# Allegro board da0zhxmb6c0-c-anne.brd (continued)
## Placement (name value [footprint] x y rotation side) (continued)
PR77  0_4  [R0402]  136.16 111.76 180 bottom
PR78  2.26k/f_4  [R0402]  118.49 49.49 180 bottom
PR79  301/f_4  [R0402]  129.38 52.25 180 top
PR80  *0_4  [R0402]  136.16 110.8 180 bottom
PR81  619/f_4  [R0402]  118.63 48.22 270 bottom
PR82  100k/f_4  [R0402]  127.37 52.21 180 bottom
PR83  301/f_4  [R0402]  118.24 46.31 270 top
PR84  649/f_4  [R0402]  117.29 46.31 90 top
PR85  200/f_4  [R0402]  118.62 48.22 90 top
PR86  *4.7_6  [R0603]  89.67 24.35 270 top
PR87  0_4  [R0402]  116.71 51.4 0 bottom
PR88  1/f_4  [R0402]  129.38 52.25 0 bottom
PR89  976/f_4  [R0402]  116.71 50.45 180 top
PR90  100/j_4  [R0402]  35.54 47.36 0 bottom
PR91  10k_4  [R0402]  96.22 28.3 0 bottom
PR92  316k/f_4  [R0402]  95.51 29.3 0 bottom
PR93  0_4  [R0402]  122.43 48.22 90 top
PR94  2.1k/f_4  [R0402]  117.66 48.22 90 bottom
PR95  15.4k/f_4  [R0402]  124.75 48.22 270 top
PR96  0_4  [R0402]  87.51 27.56 180 bottom
PR97  0_4  [R0402]  87.51 28.45 180 bottom
PR98  0_4  [R0402]  121.48 48.22 270 bottom
PR99  274/f_4  [R0402]  125.7 48.22 270 top
PR100  7.5_6  [R0603]  100.73 27.07 0 top
PR101  10_6  [R0603]  97.99 26.54 180 top
PR102  100k/f_4  [R0402]  97.79 29.68 90 bottom
PR103  13.7k/f_4  [R0402]  125.7 46.46 270 top
PR104  *100k/f_4  [R0402]  34.75 53.56 90 top
PR105  *100k_4  [R0402]  98.83 29.68 90 bottom
PR106  0_4  [R0402]  122.43 48.22 90 bottom
PR107  64.9k/f_4  [R0402]  124.75 46.46 270 top
PR108  22_6  [R0603]  123.59 47.84 270 top
PR109  0_6  [R0603]  94.64 23.18 180 top
PR110  *0/short_4  [S0402]  35.38 53.54 270 bottom
PR111  10k/f_4  [R0402]  33.17 46.68 90 bottom
PR112  12k/f_4  [R0402]  34.42 53.54 90 bottom
PR113  0.01/f_0612  [RC3216]  80.65 27.65 90 bottom
PR114  *0/short_4  [S0402]  103.25 26.25 180 top
PR115  71.5k/f_4  [R0402]  33.46 53.53 90 bottom
PR116  30.1k/f_4  [R0402]  32.23 46.68 90 bottom
PR117  *0/short_4  [S0402]  103.25 25.36 180 top
PR118  *0/short_4  [S0402]  32.44 53.54 270 bottom
PR119  11k/f_4  [R0402]  98.55 21.17 90 bottom
PR120  2.2_6  [R0603]  28.62 52.39 270 bottom
PR121  *0/short_4  [S0402]  30.33 53.54 270 bottom
PR122  63.4k/f_4  [R0402]  102.5 21.69 0 top
PR123  10k_4  [R0402]  105.11 25.6 0 top
PR124  100k_4  [R0402]  101.6 19.65 270 top
PR125  100k_4  [R0402]  95.8 27.36 0 top
PR126  20_1206  [R1206]  87.86 24.84 90 top
PR127  0_6  [R0603]  104.8 21.88 0 top
PR128  *100k_4  [R0402]  102.62 26.63 270 bottom
PR129  0_4  [R0402]  105.12 26.59 180 top
PR130  *0_4  [R0402]  100.2 19.65 90 top
PR131  88.7k/f_4  [R0402]  103.03 23.06 180 top
PR132  0_4  [R0402]  30.3 46.67 270 bottom
PR133  *0_4  [R0402]  107.06 100.88 180 top
PR134  *0_4  [R0402]  114.36 105.95 90 top
PR135  *0/short_4  [S0402]  24 87.34 180 bottom
PR136  0.02/f_0612  [RC3216]  26.93 86.58 180 bottom
PR137  220_8  [R0805]  84.71 103.98 180 top
PR138  22_6  [R0603]  101.91 88.2 180 top
PR139  22_8  [R0805]  107.99 85.11 270 top
PR140  *0/short_4  [S0402]  24 86.1 180 bottom
PR141  *100k/f_6  [R0603]  118.39 103.22 180 top
PR142  1m_4  [R0402]  118.26 106.77 270 top
PR143  1m_4  [R0402]  98.55 98.77 90 top
PR144  1m_4  [R0402]  119.28 106.77 90 top
PR145  *0_6  [R0603]  144.4 94.64 180 top
PR146  0_6  [R0603]  144.4 96.01 0 top
PR147  100/f_4  [R0402]  42.55 83.66 0 top
PR148  *0/short_4  [S0402]  42.55 84.55 180 top
PR149  100/f_4  [R0402]  45.72 83.66 0 top
PR150  *0/short_4  [S0402]  45.72 84.67 0 top
PR151  0_4  [R0402]  45.21 60.54 0 bottom
PR152  150/f_4  [R0402]  46.74 59.65 270 bottom
PR153  10k/f_4  [R0402]  47.12 62.07 0 bottom
PR154  *0_4  [R0402]  45.09 69.56 180 top
PR155  10k/f_4  [R0402]  45.24 62.58 180 bottom
PR156  10k/f_4  [R0402]  137.52 97.02 180 bottom
PR157  10k/f_4  [R0402]  137.52 95.09 0 bottom
PR158  5.11k/f_4  [R0402]  45.24 61.56 0 bottom
PR159  20/f_4  [R0402]  47.12 61.05 180 bottom
PR160  3.57k/f_4  [R0402]  45.21 58.51 180 bottom
PR161  0_4  [R0402]  45.21 59.53 0 bottom
PR162  22_8  [R0805]  144.68 91.63 0 top
PR163  68k/f_4  [R0402]  44.2 61.2 0 top
PR164  *2.2_6  [R0603]  135.33 91.4 0 bottom
PR165  0_4  [R0402]  43 62.35 0 top
PR166  22_6  [R0603]  40.11 60.53 270 top
PR167  *665k/f_4  [R0402]  130.68 94.07 270 top
PR168  0_4  [R0402]  132.79 95.29 270 top
PR169  *0_4  [R0402]  130.18 95.36 180 top
PR170  2.2_6  [R0603]  38.46 69.94 180 top
PR171  *200/f_4  [R0402]  34.24 67.44 180 bottom
PR172  *75/f_4  [R0402]  36.87 64.84 270 top
PR173  6.98k/f_4  [R0402]  36.42 65.52 180 bottom
PR174  13.7k/f_4  [R0402]  36.42 63.44 0 bottom
PR175  1.1k/f_4  [R0402]  36.37 61.38 0 bottom
PR176  22.1k/f_4  [R0402]  38.71 61.08 90 bottom
PR177  100k/f_4  [R0402]  40.51 83.66 270 bottom
PR178  *1m_6  [R0603]  114.81 92.55 90 top
PR179  221/f_4  [R0402]  36.42 62.47 0 bottom
PR180  20/f_4  [R0402]  37.47 58.66 0 top
PR181  1k/f_4  [R0402]  37.77 59.02 90 bottom
PR182  *2.2_6  [R0603]  128.03 61.81 0 top
PR183  *22_8  [R0805]  116.84 85.33 270 top
PR184  *2.2_6  [R0603]  40.77 75.66 90 top
PR185  100k/f_4  [R0402]  123.48 57.78 270 bottom
PR186  *1m_6  [R0603]  116.21 92.55 90 top
PR187  200/f_4  [R0402]  34.32 67.43 180 top
PR188  301/f_4  [R0402]  34.24 66.47 0 bottom
PR189  *1m_6  [R0603]  111.76 92.55 90 top
PR190  *1m_6  [R0603]  113.23 92.55 90 top
PR191  2.2_4  [R0402]  127.12 56.35 180 bottom
PR192  *2.2_6  [R0603]  129.44 109.67 90 bottom
PR193  887k/f_4  [R0402]  127.37 56.35 0 top
PR194  22_8  [R0805]  105.62 110.86 0 top
PR195  0_4  [R0402]  118.48 54.7 180 bottom
PR196  10k/f_4  [R0402]  118.49 51.53 180 top
PR197  *200/f_4  [R0402]  129.38 53.29 0 top
PR198  6.98k/f_4  [R0402]  127.37 54.36 180 bottom
PR199  6.49k/f_4  [R0402]  127.37 55.4 180 bottom
PR200  *0/short_4  [S0402]  118.59 50.51 0 top
PR201  1m_6  [R0603]  97.66 104.87 270 top
PR202  16/f_4  [R0402]  116.71 51.4 180 top
PR203  402/f_4  [R0402]  129.38 53.29 180 bottom
PR204  *75/f_4  [R0402]  127.37 52.25 0 top
PR205  1.1k/f_4  [R0402]  125.7 48.22 90 bottom
PR206  64.9/f_4  [R0402]  125.7 46.46 270 bottom
PR207  *0_4  [R0402]  119.57 48.22 270 bottom
PR208  1.58k/f_4  [R0402]  124.75 46.46 90 bottom
PR209  22.1k/f_4  [R0402]  124.75 48.22 90 bottom
PR210  *0/short_4  [S0402]  111.01 61.81 180 top
PR211  100/f_4  [R0402]  111 60.67 180 top
PR212  68k/f_4  [R0402]  120.52 48.22 270 top
PR213  *0/short_4  [S0402]  111.01 62.83 180 top
PR214  10k/f_4  [R0402]  121.48 48.22 90 top
PR215  0_4  [R0402]  120.52 46.44 90 top
PR216  100/f_4  [R0402]  112.4 62.32 270 top
PR217  1m_6  [R0603]  102.5 109.4 0 top
PR218  *1m_6  [R0603]  105.07 109.17 180 top
PR219  1m_6  [R0603]  102.54 110.85 180 top
PR220  0_4  [R0402]  100.58 31.5 270 top
PR221  *10k_4  [R0402]  98.67 31.5 270 top
PR222  *0_4  [R0402]  99.62 31.5 90 top
PR223  1m_4  [R0402]  67.08 18.71 90 top
PR224  *0_4  [R0402]  68.35 18.68 270 top
PR225  100_4  [R0402]  74.04 20.46 90 top
PR226  100_4  [R0402]  69.42 20.46 90 top
PR227  100_4  [R0402]  68.35 20.46 90 top
PR228  100k_4  [R0402]  95.1 30.57 0 top
PR229  33k/f_4  [R0402]  86.17 23.58 270 top
PR230  10k_4  [R0402]  58.8 25.87 270 bottom
PR231  *2.2_6  [R0603]  26.37 44.7 180 top
PR232  0_4  [R0402]  115.25 105.95 90 top
PR233  *0_4  [R0402]  113.47 105.95 90 top
PR234  0_4  [R0402]  44.43 67.58 270 bottom
PR235  *0_4  [R0402]  43.36 71.34 270 top
PR236  *0_4  [R0402]  118.48 53.72 0 top
PR237  *0_4  [R0402]  31.37 53.56 270 bottom
PR238  22_6  [R0603]  101.91 89.6 180 top
PR239  100k/f_4  [R0402]  91.77 102.71 180 bottom
PR240  100k/f_4  [R0402]  91.77 103.72 180 bottom
PR241  100k/f_4  [R0402]  91.77 99.91 180 bottom
PR242  100k/f_4  [R0402]  91.77 100.93 180 bottom
PU1  rt5041agqw  [QFN28-4X4-4-29P-RT5041A]  113.77 101.74 0 bottom
PU2  as393mtr-e1  [SOIC8-6-1_27]  115.7 39.84 180 bottom
PU3  nb670gq-z  [QFN14-3X3-4-16P]  134.11 95.09 0 bottom
PU4  rt8175agqw  [QFN32-4X4-4-33P-RT8171B]  40.69 65.52 180 bottom
PU5  nb671gq-z  [QFN14-3X3-4-16P]  134.16 106.29 270 bottom
PU6  rt8175agqw  [QFN32-4X4-4-33P-RT8171B]  122.94 52.67 0 top
PU7  tps51716rukr  [TQFN20-3X3-4-21P]  31.98 50.1 270 bottom
PU8  bq24737rgrr  [PVQFN20-3_5X3_5-5-25P]  99.06 22.98 0 top
Q1  pj4n3kdw  [SC70-2_1-65-6P]  19.1 82.48 90 top
Q2  2n7002  [SOT23_213-3_3-2]  15.13 86.74 270 bottom
Q3  2n7002k  [SOT23_213-3_3-2]  41.91 25.62 0 bottom
Q5  2n7002k  [SOT23_213-3_3-2]  44.83 28.16 0 bottom
Q6  *2n7002dw  [SC70-2_1-65-6P]  7.49 29.61 180 top
Q7  *pja138k  [SOT23_213-3_3-2]  12.19 30.44 90 top
Q10  2n7002k  [SOT23_213-3_3-2]  72.9 102.07 90 top
Q11  *pja138k  [SOT23_213-3_3-2]  28.07 22.95 90 top
Q12  pja138k  [SOT23_213-3_3-2]  148.08 27.52 0 top
Q13  *pj4n3kdw  [SC70-2_1-65-6P]  149.61 38.7 90 top
Q14  ap2331sa-7  [SOT23_213-3_3-2]  14.99 86.55 270 top
Q15  pja138k  [SOT23_213-3_3-2]  34.32 93.36 0 bottom
Q16  2n7002k  [SOT23_213-3_3-2]  31.75 90.57 90 bottom
Q17  pja138k  [SOT23_213-3_3-2]  39.78 89.27 90 bottom
Q19  2n7002k  [SOT23_213-3_3-2]  19.02 75.53 0 top
Q21  2n7002k  [SOT23_213-3_3-2]  88.6 94.81 0 bottom
Q22  pja138k  [SOT23_213-3_3-2]  38.05 93.39 90 bottom
Q23  2n7002k  [SOT23_213-3_3-2]  82.93 90.9 270 bottom
Q24  dtc144eua  [UMT_213-3-1_3]  38.36 25.87 0 bottom
Q25  *ac@pja138k  [SOT23_213-3_3-2]  145.83 79.91 270 top
Q27  ac@ao3413  [SOT23_213-3_3-2]  151.92 102.75 270 top
Q31  mmbt3904-7-f_200ma  [SOT23_213-3_3-2]  140.72 100.68 0 top
Q32  *pja138k  [SOT23_213-3_3-2]  101.6 89.31 270 bottom
Q33  *pja138k  [SOT23_213-3_3-2]  98.71 93.08 270 top
Q34  *pja138k  [SOT23_213-3_3-2]  79 90.9 270 bottom
Q35  pj4n3kdw  [SC70-2_1-65-6P]  110.62 41.62 90 bottom
Q36  *pj4n3kdw  [SC70-2_1-65-6P]  102.88 82.66 90 bottom
Q38  pj4n3kdw  [SC70-2_1-65-6P]  106.31 82.79 90 bottom
Q39  dtc144eua  [UMT_213-3-1_3]  92.33 93.18 90 bottom
Q40  2n7002k  [SOT23_213-3_3-2]  126.69 40.9 270 bottom
Q41  2n7002  [SOT23_213-3_3-2]  41.4 25.36 0 top
Q42  2n7002  [SOT23_213-3_3-2]  39.37 22.7 180 top
Q43  gs@dtc144eua  [UMT_213-3-1_3]  89.41 82.64 270 top
Q44  2n7002k  [SOT23_213-3_3-2]  44.58 22.82 0 top
Q45  *ao3413  [SOT23_213-3_3-2]  48.97 24.54 0 top
Q53  *hd@pja138k  [SOT23_213-3_3-2]  148.87 58.38 90 top
Q54  *ao3413  [SOT23_213-3_3-2]  62.31 96.74 270 top
Q65  pja138k  [SOT23_213-3_3-2]  145.83 83.61 270 top
Q75  2n7002k  [SOT23_213-3_3-2]  96.9 89.12 90 bottom
Q76  2n7002k  [SOT23_213-3_3-2]  92.97 89.5 0 bottom
Q77  hub@ao3413  [SOT23_213-3_3-2]  25.91 29.68 270 top
Q78  hub@2n7002k  [SOT23_213-3_3-2]  22.73 31.46 90 top
Q79  pja138k  [SOT23_213-3_3-2]  104.99 88.61 0 top
R2  *100/f_4  [R0402]  14.1 79.18 270 bottom
R3  *100/f_4  [R0402]  14.1 81.21 270 bottom
R4  *100/f_4  [R0402]  14.1 75.12 270 bottom
R5  *100/f_4  [R0402]  14.1 77.15 270 bottom
R6  2.2k_4  [R0402]  19.31 85.05 180 top
R7  2.2k_4  [R0402]  19.31 80.07 0 top
R10  100k/f_4  [R0402]  16 83.88 270 bottom
R11  *0/short_4  [S0402]  16.28 53.23 180 bottom
R12  *0/short_4  [S0402]  16.28 54.25 180 bottom
R13  *0/short_4  [S0402]  16.36 59.81 180 bottom
R14  *0/short_4  [S0402]  16.36 60.82 180 bottom
R15  *0/short_4  [S0402]  16.28 56.66 180 bottom
R16  *0/short_4  [S0402]  16.28 57.67 180 bottom
R17  2.2_6  [R0603]  153.57 105.01 90 top
R18  *10k_4  [R0402]  54.87 72.13 0 bottom
R19  10k_4  [R0402]  17.63 86.96 90 bottom
R20  47/f_6  [R0603]  15.62 46.5 90 bottom
R21  47/f_6  [R0603]  15.62 43.84 270 bottom
R22  *10k_4  [R0402]  54.87 73.14 0 bottom
R23  4.7k_4  [R0402]  51.82 74.26 0 bottom
R25  10k_4  [R0402]  15.43 23.33 270 top
R26  4.7k_4  [R0402]  17.32 43.27 180 bottom
R28  4.7k_4  [R0402]  17.27 47.08 180 bottom
R29  200k/f_4  [R0402]  10.14 22.44 0 top
R30  4.7k_4  [R0402]  51.82 75.28 0 bottom
R32  4.7k_4  [R0402]  14.55 23.33 90 top
R33  10k_4  [R0402]  80.28 87.75 90 bottom
R34  10k_4  [R0402]  85.36 87.75 90 bottom
R35  *ac@10k_4  [R0402]  89.43 87.75 90 bottom
R36  *10k_4  [R0402]  88.42 87.75 90 bottom
R37  tpm@10k_4  [R0402]  87.4 87.75 90 bottom
R38  20k/j_4  [R0402]  143.89 99.72 0 top
R39  10k_4  [R0402]  96.32 78.21 270 top
R40  10k_4  [R0402]  86.38 87.75 90 bottom
R41  100k/j_4  [R0402]  11.94 22.44 0 top
R42  33_4  [R0402]  80.85 93.69 270 bottom
R43  *10k_4  [R0402]  54.87 71.08 0 bottom
R44  *0_4  [R0402]  56.52 86.96 180 bottom
R45  *0_4  [R0402]  56.52 85.82 180 bottom
R46  *20k/j_4  [R0402]  56.52 88.71 0 bottom
R47  4.7k_4  [R0402]  54.87 70.07 0 bottom
R48  *10k_4  [R0402]  51.82 73.24 0 bottom
R49  *0/short_6  [S0603]  76.58 88.48 270 bottom
R50  10k_4  [R0402]  87.5 81.88 90 bottom
R51  nac@10k_4  [R0402]  89.45 85.98 90 bottom
R52  10k_4  [R0402]  88.38 85.98 90 bottom
R53  ntpm@10k_4  [R0402]  87.39 85.98 90 bottom
R54  *10k_4  [R0402]  86.38 85.98 90 bottom
R55  *10k_4  [R0402]  84.73 85.98 90 bottom
R56  10k_4  [R0402]  92.84 82.98 180 top
R57  10k_4  [R0402]  77.8 88.08 270 bottom
R58  20k/j_4  [R0402]  145.67 99.72 180 top
R59  *10k_4  [R0402]  99.06 90.8 180 top
R60  113/f_4  [R0402]  58.66 86.1 90 bottom
R61  0_4  [R0402]  58.9 87.59 0 bottom
R62  *0_4  [R0402]  59.66 86.1 270 bottom
R63  22_4  [R0402]  16.26 19.99 270 top
R64  *10k_4  [R0402]  51.82 72.1 0 bottom
R65  2.2k_4  [R0402]  17.53 48.86 90 top
R66  2.2k_4  [R0402]  6.99 36.54 0 top
R67  100k/f_4  [R0402]  3.31 20.18 180 top
R68  10_4  [R0402]  119.64 90.01 180 bottom
R69  *10k_6_ntc  [R0603]  86.97 91.89 180 bottom
R70  10_4  [R0402]  104.14 88.74 270 bottom
R71  0_4  [R0402]  47.63 27.9 180 bottom
R72  0_4  [R0402]  47.63 28.79 180 bottom
R73  *100k_4  [R0402]  47.63 27.02 0 bottom
R74  *0_4  [R0402]  13.67 17.58 0 top
R75  10_4  [R0402]  119.64 88.99 180 bottom
R76  *1k/j_4  [R0402]  51.82 71.08 180 bottom
R77  3.3k/f_4  [R0402]  104.65 90.26 180 bottom
R78  *0/j_4  [R0402]  88.11 90.11 90 bottom
R79  *10k_4  [R0402]  85.95 90.11 90 bottom
R80  10k_4  [R0402]  89.13 85.93 270 top
R81  10k_4  [R0402]  94.5 84.77 90 bottom
R83  22_4  [R0402]  13.67 16.63 0 top
R84  10_4  [R0402]  120.27 87.59 270 bottom
R85  10_4  [R0402]  106.76 89.25 0 bottom
R92  3.3k/f_4  [R0402]  119.25 87.59 270 bottom
R93  *10k_4  [R0402]  53.34 70.2 270 bottom
R96  33_4  [R0402]  106.76 87.98 0 bottom
R97  100k_4  [R0402]  49.91 67.91 0 bottom
R98  10k_4  [R0402]  97.34 78.21 270 top
R99  10k_4  [R0402]  98.35 78.21 270 top
R100  100_4  [R0402]  77.9 77.54 270 top
R101  10k_4  [R0402]  92.06 81.14 90 top
R102  3.3k/f_4  [R0402]  105.33 88.28 90 bottom
R103  *4.7k_4  [R0402]  51.94 67.91 0 bottom
R104  *100k/f_4  [R0402]  68 95.44 180 top
R105  1k_4  [R0402]  27.43 19.65 0 top
R106  *0/short_4  [S0402]  74.4 98.19 270 top
R107  *100k/j_4  [R0402]  13.46 28.54 90 top
R108  *100k/f_4  [R0402]  69.83 95.44 0 top
R109  *0/short_4  [S0402]  73.38 98.19 270 top
R110  100k_4  [R0402]  48.02 73.4 180 bottom
R111  *10k_4  [R0402]  50.03 73.4 180 bottom
R112  22_4  [R0402]  92.6 79.03 0 bottom
R113  51/f_4  [R0402]  60.3 72.23 180 top
R114  *0_4  [R0402]  64.26 101.31 180 top
R115  51/f_4  [R0402]  51.18 72.86 270 top
R116  100k_4  [R0402]  48.02 74.42 180 bottom
R117  *10k_4  [R0402]  49.95 74.42 180 bottom
R118  hub@0_4  [R0402]  75.52 98.16 90 top
R119  hub@0_4  [R0402]  76.53 98.16 90 top
R120  *22_4  [R0402]  92.61 78.06 0 bottom
R121  tpm@22_4  [R0402]  94.38 78.54 0 bottom
R122  *10k_4  [R0402]  49.93 75.69 180 bottom
R123  100k_4  [R0402]  48.02 75.69 180 bottom
R124  *10k_4  [R0402]  15.37 29.43 180 top
R125  *100k_4  [R0402]  15.37 30.7 0 top
R126  22_4  [R0402]  90.85 77.84 0 bottom
R127  100k_4  [R0402]  49.91 66.77 0 bottom
R128  ac@10k_4  [R0402]  147.07 101.31 90 top
R129  *0_6  [R0603]  67.31 101.82 270 top
R130  0_6  [R0603]  68.84 101.82 270 top
R131  *10k_4  [R0402]  51.82 66.77 180 bottom
R132  20k_4  [R0402]  50 72.25 180 bottom
R135  tpm@2.2_6  [R0603]  127.64 70.96 270 bottom
R136  *0/short_4  [S0402]  47.99 71.31 180 bottom
R137  2.2/f_4  [R0402]  44.96 88.12 0 bottom
R138  *200/f_4  [R0402]  45.98 69.69 0 bottom
R139  0_4  [R0402]  43.94 69.69 0 bottom
R141  2.2/f_4  [R0402]  44.96 87.02 0 bottom
R142  200/f_4  [R0402]  45.98 70.58 0 bottom
R143  0_4  [R0402]  43.94 70.88 0 bottom
R144  2.2/f_4  [R0402]  43.11 87.02 180 bottom
R146  2.2/f_4  [R0402]  43.13 85.89 180 bottom
R147  *301/f_4  [R0402]  45.98 71.59 180 bottom
R148  0_4  [R0402]  43.94 71.9 0 bottom
R149  tpm_n@0_4  [R0402]  141.74 72.44 0 bottom
R150  *1k/j_4  [R0402]  88.43 75.47 180 bottom
R151  *1k/j_4  [R0402]  87.96 74.03 270 bottom
R154  *1k/j_4  [R0402]  90.82 74.56 270 bottom
R155  *1k/j_4  [R0402]  91.49 73.22 180 bottom
R156  *1k/j_4  [R0402]  89.71 72.3 180 bottom
R157  *1k/j_4  [R0402]  92.08 71.77 270 bottom
R158  *1k/j_4  [R0402]  93.17 71.77 270 bottom
R159  *tpm_i@0_4  [R0402]  141.35 71.1 90 bottom
R160  100k/f_4  [R0402]  91.85 85.08 270 bottom
R161  0_4  [R0402]  102.54 75.16 90 top
R163  *100k_4  [R0402]  98.68 87.72 180 bottom
R164  0_4  [R0402]  95.05 65.42 90 bottom
R165  10k_4  [R0402]  94.18 67.9 0 bottom
R166  0_4  [R0402]  91.83 86.78 270 bottom
R167  100k/f_4  [R0402]  101.52 75.16 90 top
R168  3.3k/f_4  [R0402]  136.27 56.48 90 bottom
R169  *0_4  [R0402]  96.55 72.76 90 bottom
R170  *10k_4  [R0402]  89.79 69.81 90 top
R171  *1k/j_4  [R0402]  94.18 70.31 180 bottom
R172  2.7k_4  [R0402]  94.18 69.36 0 bottom
R173  10k_4  [R0402]  93.42 66.89 180 bottom
R174  *1k_4  [R0402]  109.74 40.86 0 top
R175  3.3k/f_4  [R0402]  133.73 56.48 90 bottom
R176  0_4  [R0402]  133.42 40.05 270 bottom
R177  *0_4  [R0402]  92.84 86.78 270 bottom
R178  *0_4  [R0402]  103.68 75.16 90 top
R180  *1k/j_4  [R0402]  97.6 67.4 90 bottom
R181  *0/short_4  [S0402]  90.3 68.88 180 bottom
R182  10k/f_4  [R0402]  100.47 67.37 90 bottom
R183  *10k_4  [R0402]  138.91 50.38 270 bottom
R184  3.3k/f_4  [R0402]  134.11 43 270 bottom
R186  *1k/j_4  [R0402]  96.64 67.02 90 bottom
R188  0_4  [R0402]  94.52 75.51 0 bottom
R189  *1k/j_4  [R0402]  99.5 67.4 90 bottom
R191  0_4  [R0402]  94.87 73.4 0 bottom
R193  *1k/j_4  [R0402]  98.55 67.4 90 bottom
R194  1k/j_4  [R0402]  99.53 65.54 270 bottom
R196  1k/j_4  [R0402]  88.48 65.9 0 top
R197  *1k_4  [R0402]  111.73 39.59 0 top
R198  1k/j_4  [R0402]  98.32 65.54 270 bottom
R199  *1k_4  [R0402]  109.74 39.72 180 top
R200  *10k_4  [R0402]  80.07 68.56 90 top
R201  *10k_4  [R0402]  90.93 69.81 90 top
R202  75/f_4  [R0402]  98.22 71.54 180 bottom
R203  75/f_4  [R0402]  99.21 69.23 180 bottom
R206  75/f_4  [R0402]  96.65 69.13 180 bottom
R208  75/f_4  [R0402]  98.55 70.42 180 bottom
R209  0_4  [R0402]  127 42.89 90 top
R210  100k_4  [R0402]  131.95 43.27 270 top
R212  4.7k_4  [R0402]  137.16 43.27 270 top
R213  4.7k_4  [R0402]  138.11 43.27 270 top
R214  10k_4  [R0402]  138.81 45.81 270 top
R215  *4.7k_4  [R0402]  134.11 43.27 270 top
R216  *4.7k_4  [R0402]  135.25 43.27 270 top
R218  *10k_4  [R0402]  136.69 43.65 0 bottom
R220  *0/short_4  [S0402]  93.55 84.22 90 bottom
R221  10k_4  [R0402]  97.21 84.91 270 bottom
R222  0_4  [R0402]  145.42 33.14 90 top
R223  10k_4  [R0402]  96.12 64.41 90 bottom
R224  10k_4  [R0402]  102.36 68.16 0 top
R225  10k_4  [R0402]  100.84 69.56 90 top
R226  10k_4  [R0402]  102.36 69.18 0 top
R227  10k/f_4  [R0402]  70.36 102.2 90 top
R231  10k_4  [R0402]  94.02 82.21 90 bottom
R232  *0_4  [R0402]  96.1 84.9 270 bottom
R233  0_4  [R0402]  145.8 35.37 180 top
R235  *10k_4  [R0402]  123.95 31.59 0 top
R236  *0_4  [R0402]  137.15 77.31 0 top
R238  *0_4  [R0402]  132.15 78.99 0 top
R239  *0_4  [R0402]  131.77 79.96 0 top
R241  *0_4  [R0402]  133.47 77.16 90 top
R244  0_4  [R0402]  145.34 30.34 270 top
R245  *0_4  [R0402]  137.16 76.36 0 top
R247  0_4  [R0402]  132.59 36.41 90 bottom
R248  10k_4  [R0402]  146.36 30.34 270 top
R249  *22_4  [R0402]  128.61 36.41 270 bottom
R250  100k_4  [R0402]  131.24 36.41 270 bottom
R252  *10k_4  [R0402]  27.43 20.54 180 top
R254  100k_4  [R0402]  123.95 26.76 0 top
R255  *0_4  [R0402]  123.95 25.75 0 top
R256  0_4  [R0402]  123.95 24.6 180 top
R257  *10k_4  [R0402]  148.08 42.38 90 top
R259  *0_4  [R0402]  150.12 42.38 90 top
R260  0_6  [R0603]  32.74 26.84 180 top
R261  0_6  [R0603]  32.74 25.06 180 top
R262  0_6  [R0603]  32.74 23.41 180 top
R263  0_6  [R0603]  32.74 21.63 180 top
R266  33_4  [R0402]  7.7 4.94 270 top
R267  150/f_4  [R0402]  6.88 3.04 270 top
R268  2.2k_4  [R0402]  17.27 82.36 270 bottom
R269  2.2k_4  [R0402]  17.27 84.14 90 bottom
R270  620/f_4  [R0402]  14.48 77.66 0 top
R271  620/f_4  [R0402]  14.48 76.64 0 top
R272  620/f_4  [R0402]  14.48 75.63 0 top
R273  620/f_4  [R0402]  14.48 74.61 0 top
R274  620/f_4  [R0402]  14.48 81.72 0 top
R275  620/f_4  [R0402]  14.48 80.71 0 top
R276  620/f_4  [R0402]  14.48 79.69 0 top
R277  620/f_4  [R0402]  14.48 78.67 0 top
R278  *0_4  [R0402]  42.57 92.83 270 bottom
R279  10k_4  [R0402]  36.07 95.98 180 bottom
R280  *100k_4  [R0402]  42.55 90.92 90 bottom
R281  *100k_4  [R0402]  152.04 100.32 180 top
R282  10k_4  [R0402]  40.49 86.96 180 bottom
R289  *100k/f_4  [R0402]  21.46 75.5 270 top
R290  *100k_4  [R0402]  35.61 90.92 0 bottom
R293  10k_4  [R0402]  38.74 27.9 0 bottom
R294  *100k_4  [R0402]  41.12 93.56 0 bottom
R295  *0/short_4  [S0402]  31.37 93.06 180 bottom
R297  *ac@0_4  [R0402]  155.7 100.04 0 top
R299  10k_4  [R0402]  84.62 92.44 180 bottom
R300  10k_4  [R0402]  40.84 91.84 180 bottom
R301  *10k_4  [R0402]  38.74 28.79 180 bottom
R302  nac@0_4  [R0402]  153.82 98.97 0 top
R303  *0_6  [R0603]  86.36 86.71 90 top
R304  10m_4  [R0402]  73.28 86.96 180 bottom
R305  *10k_4  [R0402]  78.26 85.97 90 bottom
R306  *10k_4  [R0402]  40.77 28.79 180 bottom
R307  *10k_4  [R0402]  78.88 87.75 90 bottom
R308  0_4  [R0402]  84.46 87.72 90 bottom
R309  0_6  [R0603]  84.84 86.71 90 top
R310  10k_4  [R0402]  40.77 27.9 180 bottom
R311  200k/f_4  [R0402]  70.22 85.56 0 bottom
R312  *0/short_6  [S0603]  58.55 78.7 90 top
R313  *short_8  [S0805]  53.98 80.23 180 top
R314  *0/short_6  [S0603]  54.36 73.88 0 top
R315  *0/short_6  [S0603]  53.62 72 0 top
R316  *0/short_6  [S0603]  53.34 84.04 90 top
R317  10k_4  [R0402]  109.42 100.88 0 top
R318  0_6  [R0603]  82.93 86.71 90 top
R319  *short_8  [S0805]  70.87 85.44 90 top
R320  *10k_4  [R0402]  106.87 79.47 270 bottom
R321  0_4  [R0402]  8.64 36.16 90 top
R322  *1k_4  [R0402]  92.46 95.47 0 bottom
R323  *0/short_6  [S0603]  66.47 87.87 180 top
R324  *0/short_6  [S0603]  80.42 87.04 270 top
R325  *0/short_6  [S0603]  75.19 86.96 270 top
R326  *0/short_6  [S0603]  76.84 86.96 270 top
R327  0_4  [R0402]  18.16 41.32 180 bottom
R328  0_4  [R0402]  89.03 81.24 0 bottom
R329  *0_4  [R0402]  89.03 82.26 0 bottom
R331  *ac@4.7k_4  [R0402]  148.08 80.23 270 top
R332  *0_4  [R0402]  137.16 75.4 0 top
R333  *49.9/f_4  [R0402]  63.88 81.75 180 top
R334  *0/short_6  [S0603]  53.98 78.32 0 top
R336  *0/short_4  [S0402]  10.16 25.87 180 top
R337  nac@0_8  [R0805]  148.31 104.14 180 top
R338  *0/short_6  [S0603]  53.98 82.01 0 top
R339  *0/short_4  [S0402]  18.16 41.11 180 top
R340  10k/f_4  [R0402]  74.02 82.3 270 top
R341  402/f_4  [R0402]  62.49 79.59 270 top
R342  402/f_4  [R0402]  66.29 79.97 90 top
R343  402/f_4  [R0402]  68.96 81.88 180 top
R344  402/f_4  [R0402]  71.63 80.61 90 top
R346  80.6_4  [R0402]  81.56 78.33 90 top
R347  *0/short_6  [S0603]  60.07 76.29 0 top
R349  *10k_4  [R0402]  80.06 78.3 270 top
R350  *0/short_4  [S0402]  10.17 24.92 180 top
R351  *ac@0_4  [R0402]  142.69 76.31 270 top
R352  45.3/f_4  [R0402]  64.84 77.41 90 top
R353  *0/short_6  [S0603]  89.64 79.05 180 top
R354  *0/short_6  [S0603]  55.63 75.28 0 top
R355  402/f_4  [R0402]  69.44 78.45 90 top
R356  51/f_4  [R0402]  49.93 70.2 180 bottom
R357  51/f_4  [R0402]  52.2 74.64 270 top
R358  51/f_4  [R0402]  51.18 74.64 270 top
R359  10k_4  [R0402]  49.93 68.96 180 bottom
R360  *0_4  [R0402]  143.71 76.31 270 top
R361  49.9/f_4  [R0402]  75.08 77.76 90 top
R362  0_4  [R0402]  83.57 77.94 270 top
R363  100/f_4  [R0402]  85.19 76.55 180 top
R364  *0/short_6  [S0603]  89.64 77.53 180 top
R365  *short_8  [S0805]  61.98 88.23 90 top
R366  150_4  [R0402]  61.9 75.9 90 top
R367  *10k_4  [R0402]  48.02 68.96 180 bottom
R368  100/f_4  [R0402]  62.36 69.81 180 top
R369  2.49k/f_4  [R0402]  73.29 76.85 180 top
R376  *100k_4  [R0402]  149.23 99.91 270 top
R377  *short_8  [S0805]  63.96 88.23 90 top
R378  100k/f_4  [R0402]  71.88 98.52 270 top
R381  *0/short_6  [S0603]  78.86 87.03 270 top
R382  *0/short_4  [S0402]  66.42 95.39 270 top
R384  *100k/j_4  [R0402]  47.98 89.69 180 bottom
R385  *short_8  [S0805]  65.43 93.26 180 bottom
R386  *0_4  [R0402]  70.23 73.12 90 top
R388  *0/short_4  [S0402]  19.18 28.98 180 bottom
R389  *0/short_4  [S0402]  19.6 30.95 180 bottom
R390  *0/short_4  [S0402]  19.6 32.95 180 bottom
R392  *0/short_4  [S0402]  18.84 21.25 270 bottom
R394  0_4  [R0402]  19.18 28.03 0 bottom
R395  *short_8  [S0805]  53.87 70.42 180 top
R396  *tpm_i@20k_4  [R0402]  139.83 74.13 0 bottom
R398  *0_6  [R0603]  93.83 67.82 0 top
R399  *tpm_i@4.7k_4  [R0402]  139.84 71.47 180 bottom
R400  150k/f_4  [R0402]  142.11 97.81 0 top
R401  *tpm_i@10k_4  [R0402]  128.6 83.35 0 bottom
R402  0_6  [R0603]  93.45 66.41 0 top
R403  *tpm_i@4.7k_4  [R0402]  139.45 72.8 270 bottom
R405  *short_8  [S0805]  57.68 93.16 270 bottom
R406  *short_8  [S0805]  55.73 93.16 270 bottom
R407  68.1k/f_4  [R0402]  142.11 96.85 180 top
R408  *tpm_i@0_4  [R0402]  139.83 74.14 180 top
R409  51/f_4  [R0402]  48.02 67.94 0 bottom
R410  4.7k/j_4  [R0402]  140.08 96.85 0 top
R411  4.7k/j_4  [R0402]  140.08 98.31 180 top
R414  *0/short_6  [S0603]  101.36 65.94 90 top
R415  tpm_n@0_4  [R0402]  129.03 69.05 270 bottom
R416  10k_4  [R0402]  90.43 91.79 90 bottom
R417  *0/short_6  [S0603]  99.99 65.94 90 top
R418  1k/j_4  [R0402]  89.43 68.43 0 top
R419  1k/j_4  [R0402]  89.3 67.48 0 top
R420  0_4  [R0402]  99.29 90.57 270 bottom
R421  182_4  [R0402]  71.71 63.82 270 top
R422  182/f_4  [R0402]  71.3 58.92 180 top
R423  *0/short_6  [S0603]  92.33 78.05 180 top
R424  *0/short_6  [S0603]  88.4 64.33 180 top
R425  *0/short_6  [S0603]  93.46 65 180 top
R426  *0/short_6  [S0603]  93.46 63.56 180 top
R427  *10k_4  [R0402]  99.91 85.75 180 bottom
R428  *10k_4  [R0402]  99.87 79.84 0 bottom
R429  *10k_4  [R0402]  100.97 92.32 270 top
R430  *10k_4  [R0402]  76.58 90.77 270 bottom
R431  0_4  [R0402]  98.04 86.39 180 bottom
R432  gs@4.7k_4  [R0402]  113.72 52.67 270 top
R433  gs@200k/f_4  [R0402]  114.67 52.67 270 top
R434  gs@4.7k_4  [R0402]  112.64 52.67 270 top
R435  *10k_4  [R0402]  126.05 42.89 270 top
R436  *0/short_6  [S0603]  71.3 46.93 90 bottom
R437  *0/short_6  [S0603]  72.77 46.95 90 bottom
R439  *10k_4  [R0402]  104.53 84.56 270 bottom
R440  10k_4  [R0402]  140.75 45.81 90 top
R441  *10k_4  [R0402]  102.76 85.25 0 bottom
R444  *0/short_6  [S0603]  97.49 64.91 180 top
R446  8987@0_6  [R0603]  136.02 39.84 90 bottom
R450  0_8  [R0805]  150.35 63.97 90 top
R451  0_4  [R0402]  104.42 82.28 270 bottom
R452  0_4  [R0402]  104.97 79.43 90 bottom
R453  0_4  [R0402]  100.97 83.55 90 bottom
R454  *0_6  [R0603]  137.8 36.97 270 bottom
R457  10k_4  [R0402]  108.71 40.86 270 bottom
R459  *2.2_6  [R0603]  123.57 38.03 180 top
R460  2.2_6  [R0603]  144.04 37.76 0 bottom
R461  *10k_4  [R0402]  100.97 81.52 90 bottom
R463  4.7k_4  [R0402]  111.01 44.67 0 bottom
R465  10k_4  [R0402]  105.92 79.43 90 bottom
R468  100k_4  [R0402]  119.79 34.74 90 top
R470  4.7k_4  [R0402]  105.86 85.33 180 bottom
R479  1k/j_4  [R0402]  141.73 103.22 0 top
R481  10k_4  [R0402]  136.44 51.09 90 top
R486  gs@0_6  [R0603]  120.65 26 0 top
R489  *0_4  [R0402]  91.4 83.1 90 top
R490  em@10k_4  [R0402]  106.49 75.74 0 bottom
R491  *10k_4  [R0402]  102.16 79.89 0 bottom
R493  10k_4  [R0402]  46.23 26 180 top
R494  *0_4  [R0402]  90.42 76.68 180 bottom
R495  10k_4  [R0402]  46.23 24.98 180 top
R496  200k/f_4  [R0402]  110.75 52.92 90 top
R497  *0_4  [R0402]  50.67 26.63 90 bottom
R498  *10k_4  [R0402]  109.53 48.1 0 bottom
R499  10k_4  [R0402]  109.53 46.19 0 bottom
R500  *em@10k_4  [R0402]  118.49 78.45 90 top
R501  *0_8  [R0805]  53.98 26 90 bottom
R502  2.2k_4  [R0402]  108.71 52.92 270 top
R503  em@0_4  [R0402]  114.17 78.7 90 top
R504  gs@10k_4  [R0402]  89.28 80.36 0 top
R505  *0_4  [R0402]  42.04 21.43 0 top
R506  2.2k_4  [R0402]  109.73 52.92 270 top
R507  0_8  [R0805]  52.07 26 90 bottom
R510  0_6  [R0603]  50.42 24.48 90 bottom
R512  10k_4  [R0402]  45.59 20.16 90 top
R513  10k_4  [R0402]  46.61 20.16 90 top
R514  gs@0_4  [R0402]  120.27 24.84 0 top
R517  em@0_4  [R0402]  119.38 72.74 0 top
R578  *hd@0_4  [R0402]  152.53 68.59 0 top
R581  *100_4  [R0402]  54.87 74.16 0 bottom
R587  33_4  [R0402]  40.39 19.78 180 top
R588  33_4  [R0402]  42.8 20.03 180 top
R598  10k_4  [R0402]  148.08 83.44 270 top
R671  *0/short_4  [S0402]  143.77 84.8 270 top
R780  *0_4  [R0402]  60.22 98.95 270 top
R781  gs@0_6  [R0603]  62.23 101.56 90 top
R782  *100k_4  [R0402]  61.19 98.95 90 top
R816  33_4  [R0402]  110.34 34.59 270 bottom
R819  33_4  [R0402]  69.85 98.52 90 top
R821  33_4  [R0402]  155.7 98.97 0 top
R990  *47k_4  [R0402]  140.57 109.47 0 top
R991  *47k_4  [R0402]  140.57 108.4 0 top
R998  100k_4  [R0402]  151.64 27.9 90 top
R999  33_4  [R0402]  155.7 97.88 0 top
R1000  33_4  [R0402]  76.76 93.61 270 bottom
R1001  33_4  [R0402]  158.12 103.34 90 top
R1005  ssd_m2_ssd@0_8  [R0805]  148.59 55.46 0 top
R1007  *10k_4  [R0402]  48.02 70.16 180 bottom
R1008  *10k_4  [R0402]  49.93 71.24 180 bottom
R1009  4.7k_4  [R0402]  51.82 68.93 0 bottom
R1010  *4.7k_4  [R0402]  51.82 69.94 0 bottom
R1011  *10k_4  [R0402]  80.58 85.96 270 bottom
R1012  *tpm_n@10k_4  [R0402]  139.45 72.8 90 top
R1013  *tpm_i@0_4  [R0402]  128.4 79.85 0 bottom
R1014  *0/short_6  [S0603]  11.53 23.87 0 top
R1017  *em@10k_4  [R0402]  116.92 76.83 0 top
R1018  *0/short_4  [S0402]  93.68 65.81 180 bottom
R1019  *0_4  [R0402]  93.68 64.86 0 bottom
R1020  *ssd@0_6  [R0603]  152.77 57.67 90 top
R1021  *hd@0_6  [R0603]  151.38 57.67 90 top
R1022  *hd@10k_4  [R0402]  146.48 56.61 270 top
R1023  4.7k_4  [R0402]  135.22 45.68 270 top
R1024  4.7k_4  [R0402]  134.1 45.68 270 top
R1025  *hd@0_4  [R0402]  146.48 58.46 270 top
R1026  gs@10k_4  [R0402]  83.33 87.75 90 bottom
R1027  ngs@10k_4  [R0402]  83.69 85.97 90 bottom
R1028  *10k_4  [R0402]  19.69 39.06 0 top
R1029  *0_4  [R0402]  100.84 90.8 0 top
R1030  2.2_6  [R0603]  123.57 36.67 180 top
R1031  *0_4  [R0402]  89.03 83.28 0 bottom
R1035  100k/f_4  [R0402]  94.36 86.83 180 bottom
R1037  *22_8  [R0805]  151.77 41.62 90 top
R1038  *0_4  [R0402]  151.77 37.81 270 top
R1039  100k/f_4  [R0402]  96.14 91.53 0 bottom
R1040  4.7k/f_4  [R0402]  36.97 44.49 180 bottom
R1041  4.7k/f_4  [R0402]  36.97 43.22 0 bottom
R1042  4.7k/f_4  [R0402]  37.23 45.12 270 top
R1043  *short_6  [S0603]  51.77 30.42 270 top
R1044  4.7k/f_4  [R0402]  37.23 47.03 270 top
R1045  240/f_4  [R0402]  39.17 43.88 270 bottom
R1046  240/f_4  [R0402]  50.75 36.43 270 top
R1047  240/f_4  [R0402]  56.93 41.72 270 bottom
R1048  240/f_4  [R0402]  71.04 42.38 270 top
R1049  80.6/f_4  [R0402]  53.66 41.44 0 bottom
R1050  80.6/f_4  [R0402]  56.61 37.98 270 top
R1051  80.6/f_4  [R0402]  56.5 39.52 0 top
R1052  80.6/f_4  [R0402]  56.51 35.9 270 top
R1053  80.6/f_4  [R0402]  55.76 39.97 0 bottom
R1054  80.6/f_4  [R0402]  55.59 44.01 180 bottom
R1055  80.6/f_4  [R0402]  56.96 43.63 270 bottom
R1056  80.6/f_4  [R0402]  55.76 39.02 0 bottom
R1057  80.6/f_4  [R0402]  52.88 35.16 270 top
R1058  80.6/f_4  [R0402]  58.82 36.56 270 top
R1059  80.6/f_4  [R0402]  54.57 48.51 180 bottom
R1060  80.6/f_4  [R0402]  56.98 43.86 270 top
R1061  80.6/f_4  [R0402]  56.97 41.03 270 top
R1062  80.6/f_4  [R0402]  56.6 42.46 0 top
R1063  80.6/f_4  [R0402]  53.31 40.04 270 bottom
R1064  80.6/f_4  [R0402]  53.75 46.25 180 bottom
R1065  80.6/f_4  [R0402]  54.18 34.25 270 top
R1066  80.6/f_4  [R0402]  51.92 36.51 270 bottom
R1067  80.6/f_4  [R0402]  51.87 36.43 270 top
R1068  80.6/f_4  [R0402]  54.1 43.46 90 bottom
R1069  80.6/f_4  [R0402]  54.81 36.15 270 top
R1070  80.6/f_4  [R0402]  53.5 45.21 0 bottom
R1071  80.6/f_4  [R0402]  55.49 45.26 180 bottom
R1072  80.6/f_4  [R0402]  53.39 37.6 270 bottom
R1073  80.6/f_4  [R0402]  54.57 47.52 180 bottom
R1074  80.6/f_4  [R0402]  56.93 50.27 90 top
R1075  80.6/f_4  [R0402]  56 50.27 90 top
R1076  chb@240/f_4  [R0402]  94.94 36.18 270 bottom
R1077  chb@240/f_4  [R0402]  74.22 44.94 90 bottom
R1078  chb@240/f_4  [R0402]  85.82 36.46 270 top
R1079  chb@80.6/f_4  [R0402]  94.79 35.39 270 top
R1080  chb@80.6/f_4  [R0402]  89.73 39 270 bottom
R1081  chb@80.6/f_4  [R0402]  91.63 39.87 180 bottom
R1082  chb@80.6/f_4  [R0402]  88.37 41.3 270 bottom
R1083  chb@80.6/f_4  [R0402]  91.25 38.2 180 bottom
R1084  chb@80.6/f_4  [R0402]  90.58 36.15 270 top
R1085  chb@80.6/f_4  [R0402]  90.68 42.93 180 bottom
R1086  chb@80.6/f_4  [R0402]  90.53 46.76 0 bottom
R1087  chb@80.6/f_4  [R0402]  90.97 41.95 180 bottom
R1088  chb@80.6/f_4  [R0402]  92.02 43.49 270 bottom
R1089  chb@80.6/f_4  [R0402]  95.83 35.39 270 top
R1090  chb@80.6/f_4  [R0402]  88.26 41.21 270 top
R1091  chb@80.6/f_4  [R0402]  90.79 40.91 180 bottom
R1092  chb@80.6/f_4  [R0402]  92.52 35.29 270 top
R1093  chb@80.6/f_4  [R0402]  88.24 36.15 270 top
R1094  chb@80.6/f_4  [R0402]  88.66 44.94 270 top
R1095  chb@80.6/f_4  [R0402]  91.65 44.9 0 bottom
R1096  chb@80.6/f_4  [R0402]  91.63 35.36 270 top
R1097  chb@80.6/f_4  [R0402]  88.29 39.35 270 top
R1098  chb@80.6/f_4  [R0402]  88.71 37.84 180 top
R1099  chb@80.6/f_4  [R0402]  89.28 36.15 270 top
R1100  chb@80.6/f_4  [R0402]  89.3 39.35 270 top
R1101  chb@80.6/f_4  [R0402]  93.41 35.36 270 top
R1102  chb@80.6/f_4  [R0402]  88.62 44.84 270 bottom
R1103  chb@80.6/f_4  [R0402]  90.02 45.76 0 bottom
R1104  chb@240/f_4  [R0402]  102.82 36.43 270 top
R1105  chb@80.6/f_4  [R0402]  89.81 48.68 0 bottom
R1106  chb@80.6/f_4  [R0402]  89.81 47.77 0 bottom
R1107  chb@4.7k/f_4  [R0402]  108.72 44.16 180 bottom
R1108  chb@4.7k/f_4  [R0402]  108.71 42.64 270 bottom
R1113  hub@0_4  [R0402]  33.15 63.34 90 top
R1114  *10k_4  [R0402]  29.34 68.54 270 bottom
R1115  *10k_4  [R0402]  28.32 68.54 270 bottom
R1116  *0/j_4  [R0402]  31.5 70.32 270 bottom
R1117  *10k_4  [R0402]  23.88 65.5 0 bottom
R1118  *10k_4  [R0402]  23.88 64.48 0 bottom
R1119  hub@10k_4  [R0402]  23.88 68.8 0 bottom
R1120  hub@100k/f_4  [R0402]  26.29 68.54 90 bottom
R1121  hub@619/f_4  [R0402]  33.78 60.42 90 top
R1122  hub@0_4  [R0402]  23.88 66.64 0 bottom
R1123  hub@10k_4  [R0402]  23.88 62.7 0 bottom
R1124  *0/j_4  [R0402]  23.75 59.65 270 bottom
R1125  *47k_4  [R0402]  24.89 59.65 270 bottom
R1126  *0_6  [R0603]  86.56 82.36 0 top
R1127  0_6  [R0603]  86.56 83.89 0 top
R1128  *1k/j_4  [R0402]  88.91 74.03 270 bottom
R1129  *1k/j_4  [R0402]  89.87 74.56 270 bottom
R1136  hub@0_4  [R0402]  34.42 62.96 270 bottom
R1137  hub@0_4  [R0402]  33.4 62.96 270 bottom
R1138  nts@0_4  [R0402]  34.42 60.42 90 bottom
R1139  nts@0_4  [R0402]  33.4 60.42 90 bottom
R1140  hub@0_4  [R0402]  27.69 57.75 90 bottom
R1141  hub@0_4  [R0402]  26.8 57.75 90 bottom
R1142  nts@0_4  [R0402]  26.8 55.59 270 bottom
R1143  nts@0_4  [R0402]  27.69 55.59 270 bottom
R1144  nts@0_8  [R0805]  30.35 30.83 90 bottom
R1145  *0/short_4  [S0402]  17.81 21.24 270 top
R1146  *0/short_4  [S0402]  20.94 21.25 270 bottom
R1147  *0/short_4  [S0402]  20.74 21.24 270 top
R1148  6.2k/f_4  [R0402]  22.76 28.41 0 bottom
R1149  *330_4  [R0402]  19.18 27.08 180 bottom
R1150  m2_ssd@0_8  [R0805]  151.26 54.44 270 top
R1152  *0_4  [R0402]  145.8 38.26 180 top
R1153  *0_4  [R0402]  145.8 37.3 180 top
R1157  *8390@0_6  [R0603]  139.19 39.84 90 bottom
R1158  8987@0_4  [R0402]  139.07 43.27 270 top
R1159  *8390@0_4  [R0402]  137.8 45.81 270 top
R1161  8987@0_6  [R0603]  134.72 36.97 270 bottom
R1162  *8390@0_6  [R0603]  134.62 39.84 90 bottom
R1163  8987@0_4  [R0402]  133.16 43.27 90 top
R1164  8987@0_4  [R0402]  130.05 43.27 90 top
R1165  *8390@0_4  [R0402]  131 43.27 90 top
R1166  *8390@0_4  [R0402]  127.95 43.27 90 top
R1167  8987@0_4  [R0402]  128.91 43.27 90 top
R1171  nlid@0_4  [R0402]  145.8 27.14 270 top
R1172  *4.7k_4  [R0402]  145.8 36.35 180 top
R1173  *4.7k_4  [R0402]  145.8 39.21 180 top
R1175  0_4  [R0402]  119.79 33.04 90 top
R1177  0_6  [R0603]  145.02 42.56 90 top
R1178  *0_6  [R0603]  146.41 42.56 90 top
R1179  *0_4  [R0402]  131.79 42.22 270 bottom
R1180  sp@10k_4  [R0402]  82.32 87.78 90 bottom
R1181  sp@10k_4  [R0402]  82.69 85.95 90 bottom
R1182  sp@10k_4  [R0402]  81.33 87.77 90 bottom
R1183  sp@10k_4  [R0402]  81.64 85.96 90 bottom
R1184  sp@10k_4  [R0402]  95.31 78.21 90 top
R1185  sp@10k_4  [R0402]  95.01 75.33 90 top
R1186  sp@10k_4  [R0402]  94.22 78.23 90 top
R1187  sp@10k_4  [R0402]  94.06 75.33 90 top
R1188  *1k_4  [R0402]  115.31 47.46 0 top
R1189  *1k_4  [R0402]  115.31 46.39 0 top
R1190  *0_4  [R0402]  113.72 50.64 90 top
R1191  *0_4  [R0402]  112.64 50.64 90 top
R1192  *1k_4  [R0402]  115.31 44.03 0 top
R1193  *1k_4  [R0402]  112.62 40.86 180 top
R1194  *1k_4  [R0402]  115.31 45.14 180 top
R1195  100k/f_4  [R0402]  136.74 57.63 90 top
R1196  *0_4  [R0402]  138.12 58.15 180 top
R1197  gs@0_4  [R0402]  120.78 22.94 180 top
R1198  gs@0_4  [R0402]  120.78 21.98 180 top
R1199  *10k_4  [R0402]  146.49 33.14 90 top
R1200  *tpm_i@10k_4  [R0402]  130.26 79.85 0 bottom
R1201  tpm_n@10k_4  [R0402]  127.6 69.28 180 bottom
R1202  0_4  [R0402]  16 11.95 90 top
R1203  0_4  [R0402]  15.37 32.67 0 top
R1204  0_4  [R0402]  145.8 29.05 180 top
R1205  hub@10k_4  [R0402]  22.48 27.9 270 top
R1206  0_4  [R0402]  65.79 101.82 90 top
R1207  0_4  [R0402]  64.26 102.33 180 top
R1209  *0/short_4  [S0402]  91.57 83.4 0 bottom
RP1  10k_10p8r  [10P8R]  132.08 33.62 270 bottom
SW2  misaki_sw_h1.5  [SW-NTC031-AB1G-A160T-4P]  141 32.85 0 bottom
SW3  lid@sw_ds-a40e(h3.8)  [SW-DS-A40E-4P]  152.2 26.4 270 bottom
T1  *pad  [TP2675]  45.18 86.2 180 bottom
T4  *pad  [TP2675]  43.49 84.79 180 bottom
T5  *pad  [TP2675]  97.48 72.78 180 bottom
TP1  *pad  [TP2675]  77.06 86.2 180 bottom
TP5  *pad  [TP2650]  101.31 68.87 270 bottom
TP6  *pad  [TP2650]  102.62 68.82 270 bottom
TP8  *  [TP2650]  135.12 41.91 0 top
TP10  *pad  [TP2650]  107.09 69.03 270 bottom
TP23  *pad  [TP2675]  141.92 78.91 90 bottom
TP24  *pad  [TP2675]  86.08 74.27 0 top
TP25  *pad  [TP2675]  130.68 78.83 90 bottom
TP26  *pad  [TP2675]  88.32 74.05 0 top
TP27  *pad  [TP2675]  146.43 78.56 90 bottom
TP28  *pad  [TP2675]  84.19 73.63 0 top
TP29  *pad  [TP2675]  87.33 72.41 0 top
TP30  *pad  [TP2675]  82.76 72.34 0 top
TP31  *pad  [TP2675]  80.84 72.51 0 top
TP32  *pad  [TP2675]  85.42 72.15 0 top
TP33  *pad  [TP2675]  62.13 72.2 0 top
TP34  *pad  [TP2675]  78.28 72.19 0 top
TP36  *pad  [TP2650]  23.06 23.13 0 bottom
TP37  *pad  [TP2650]  21.07 24.62 0 bottom
TP38  *pad  [TP2650]  22.28 26.28 0 bottom
TP46  *  [TP2650]  158.24 99.91 180 top
TP47  *pad  [TP2675]  27.94 70.45 180 bottom
TP48  *pad  [TP2675]  29.85 70.45 180 bottom
TP49  *pad  [TP2675]  24.26 63.59 180 bottom
TP50  *pad  [TP2650]  30.74 27.27 0 bottom
TP51  *pad  [TP2650]  29.92 26.25 0 bottom
TP52  *pad  [TP2650]  23.62 21.96 0 bottom
TP53  *pad  [TP2650]  24.92 21.86 0 bottom
TP54  *pad  [TP2650]  27.28 22.39 0 bottom
TP55  *pad  [TP2650]  30.61 24.86 0 bottom
TP59  *  [TP2650]  123.55 27.68 0 top
TP60  *  [TP2650]  124.67 29.39 0 top
TP61  *  [TP2650]  133.85 41.98 0 top
TP62  *  [TP2650]  133.13 22.06 0 top
TP63  *  [TP2650]  144.78 27.4 0 top
TP64  *  [TP2650]  144.68 26.03 0 top
U1  ap2822hketr-g1  [SOT23-5-2_8-95-5P-1_3H]  154.36 104.9 270 bottom
U4  alc255  [QFN48-6X6-4-49P-ALC280]  8.59 17.8 90 top
U5  spi_flash  [SOIC8-7_9-1_27]  113 88.08 90 bottom
U7  vlv_m_d/bga  [BGA1170-INTEL-BRASWELL]  71.4 70.5 270 bottom
U8  emc1412-1-aczl-tr  [MSOP8-4_9-65]  104.34 66.54 90 bottom
U9  it8987  [LQFP128-16X16-4-1_6H]  134.5 31.7 270 top
U11  *tpm_i@g2129tl1u  [SC70-2_1-65-6P]  129.41 81.63 0 bottom
U12  g5243at11u  [SOT23-2_8-95-6P]  47.39 91.85 0 bottom
U13  tpm@npct620/650_tssop28  [TSSOP28-6_4-65-SLB9635TT]  134.11 73.24 270 bottom
U14  spi_flash  [SOIC8-7_9-1_27]  135.64 50.13 0 bottom
U15  gs@pca9306  [VSSOP8-3_1-5-8P]  113.92 56.1 180 top
U16  *g2129tl1u  [SC70-2_1-65-6P]  98.94 82.91 270 bottom
U17  74lvc2g07gw  [SC70-2_1-65-6P-0_95H]  96.44 82.38 270 bottom
U18  74lvc2g07gw  [SC70-2_1-65-6P-0_95H]  112.02 46.83 0 bottom
U19  pca9306  [VSSOP8-3_1-5-8P]  110.87 54.32 0 bottom
U20  em@h26m52103fmr  [FBGA153-SAMSUNG-KLMBG4GEAC]  117 75.66 270 bottom
U21  gs@lis3dhtr  [LGA16-3X3-5]  114.68 24.48 90 top
U23  rts5170  [QFN24-4X4-5-25P-ALC5629]  26.29 26 0 bottom
U24  ram _ddr3l  [BGA96-ELPIDA-EDJ4216EBBG-DJ-F]  46.17 46.17 0 top
U25  ram _ddr3l  [BGA96-ELPIDA-EDJ4216EBBG-DJ-F]  63.95 46.17 0 top
U26  chb@ram _ddr3l  [BGA96-ELPIDA-EDJ4216EBBG-DJ-F]  81.22 46.17 0 top
U27  chb@ram _ddr3l  [BGA96-ELPIDA-EDJ4216EBBG-DJ-F]  99 46.17 0 top
U31  ram _ddr3l  [BGA96-ELPIDA-EDJ4216EBBG-DJ-F]  46.17 46.17 180 bottom
U32  ram _ddr3l  [BGA96-ELPIDA-EDJ4216EBBG-DJ-F]  63.95 46.17 180 bottom
U33  chb@ram _ddr3l  [BGA96-ELPIDA-EDJ4216EBBG-DJ-F]  99 46.17 180 bottom
U34  chb@ram _ddr3l  [BGA96-ELPIDA-EDJ4216EBBG-DJ-F]  81.22 46.17 180 bottom
U35  hub@gl850g-ohy50  [QFN28-5X5-5-29P-GL850G]  28.58 63.59 270 bottom
U36  ap2822hketr-g1  [SOT23-5-2_8-95-5P-1_3H]  21.46 58.13 90 bottom
U37  *g9090-180t11u  [SOT23-5]  138.69 55.72 90 top
U38  *m24c02-wmn6tp  [SOIC8-6-1_27]  111.25 45.43 0 top
VC1  *tvm0g5r5m220r  [C0402]  13.97 83.88 90 bottom
Y2  19.2mhz  [XTL-3_2X2_5-2_2X1_7]  69.71 88.9 0 bottom
Y3  32.768khz  [XTL-3_2X1_5-2_5-0_8H]  73.69 89.77 0 bottom
Y4  hub@12mhz  [XTL-3_2X2_5-2_2X1_8-4P]  30.74 56.86 180 bottom

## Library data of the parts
C1-C13 C20-C24 C26 C27 C30-C36 C38-C45 C47-C53 C55 C57-C65 C67-C71 C73-C76 C78-C81 C83 C86 C90 C92 C95 C97-C101 C104 C117-C120 C122-C126 C132-C135 C138-C142 C149-C170 C172 C173 C177-C180 C182 C183 C191-C196 C199 C200 C202-C204 C206-C209 C211 C214-C220 C224-C228 C231 C234 C240 C243-C245 C247-C251 C255 C256 C258-C260 C263 C264 C268-C270 C272 C274 C275 C279 C282-C284 C286-C290 C292 C297 C315-C331 C334-C340 C419 C423 C426 C427 C438 C573 C575 C576 C594-C597 C602 C694 C698 C700 C702-C709 C711-C719 C725-C762 C764-C766 C769 C773-C781 C783-C795 C798-C808 C812-C819 C828 C839-C841 C859-C862 C864-C878 C880 D2 D3 D23-D30 D42-D44 PC18 PC29 PC30 PC34 PC35 PC37 PC40 PC41 PC43 PC45 PC46 PC48 PC51-PC56 PC60 PC65-PC69 PC71-PC74 PC76 PC78-PC80 PC83 PC85 PC87 PC89 PC90 PC93 PC97 PC100-PC102 PC105-PC107 PC111 PC127 PC129 PC135 PC138 PC140 PC142 PC144-PC148 PC151 PC153-PC164 PC166-PC168 PC170-PC172 VC1 = C0402
C14 C16 = C1206
C15 C17-C19 C25 C28 C56 C91 C94 C121 C128-C131 C143-C148 C171 C188 C201 C205 C221-C223 C229 C230 C235-C239 C241 C242 C252-C254 C257 C261 C262 C265-C267 C271 C273 C278 C294 C314 C333 C420 C425 C601 C603 C604 C710 C720-C724 C763 C767 C768 C770-C772 C782 C842 C863 C879 PC1-PC5 PC10-PC17 PC19-PC24 PC26-PC28 PC31-PC33 PC50 PC57 PC58 PC61 PC62 PC70 PC81 PC82 PC84 PC86 PC95 PC96 PC103 PC104 PC108-PC110 PC114-PC123 PC128 PC130 PC132-PC134 PC141 PC152 PC165 PC174 = C0603
C108 PC9 PC49 = C3528
C213 C232 C233 PC6-PC8 PC25 PC39 PC47 PC63 PC64 PC77 PC91 PC92 PC94 PC99 PC112 PC124-PC126 PC131 PC136 PC137 PC139 PC143 PC149 PC150 PC169 PC173 PC175-PC177 = C0805
C829-C832 = C0201
CN1 = USB-53065-00902-001-9P-SMT
CN2 = HDMI-80103-1121-19P-LDV-SMT
CN3 = AF712L-A2G1T-12P-L-SMT
CN5 = NGFF-51749-0750P-105-75P-KE
CN6 = PHJK-2SJ3080-088111F-6P
CN7 = ML1220-SMT
CN9 = SATA-C166FQ-12208-L-22P-R
CN10 = LVDS-107K40-100011-G2-40P-L
CN11 = 50584-0280N-V01-28P-L
CN12 = 88513-0801-8P-L
CN13 = 50281-0040N-001-4P-L
CN16 = SDCARD-156-2001902600-11P-SMT
CN18 = NGFF-APCI0018-P002A-75P-KB-SMT
D5 D12 G1 L2 L3 L7 L8 PR11 PR12 PR17 PR18 PR31 PR35 PR56 PR57 PR59 PR86 PR100 PR101 PR108 PR109 PR120 PR127 PR138 PR141 PR145 PR146 PR164 PR166 PR170 PR178 PR182 PR184 PR186 PR189 PR190 PR192 PR201 PR217-PR219 PR231 PR238 R17 R20 R21 R69 R129 R130 R135 R260-R263 R303 R309 R318 R398 R402 R446 R454 R459 R460 R486 R510 R781 R1020 R1021 R1030 R1126 R1127 R1157 R1161 R1162 R1177 R1178 = R0603
D7-D10 D13-D15 D18-D22 PD1-PD3 PD9 PD10 = DSM
D11 L5 L6 L9-L11 PR1-PR9 PR13-PR16 PR20 PR21 PR24-PR30 PR32-PR34 PR36 PR37 PR39-PR55 PR58 PR62-PR85 PR87-PR99 PR102-PR107 PR111 PR112 PR115 PR116 PR119 PR122-PR125 PR128-PR134 PR142-PR144 PR147 PR149 PR151-PR161 PR163 PR165 PR167-PR169 PR171-PR177 PR179-PR181 PR185 PR187 PR188 PR191 PR193 PR195-PR199 PR202-PR209 PR211 PR212 PR214-PR216 PR220-PR230 PR232-PR237 PR239-PR242 R2-R7 R10 R18 R19 R22 R23 R25 R26 R28-R30 R32-R48 R50-R68 R70-R81 R83-R85 R92 R93 R96-R105 R107 R108 R110-R128 R131 R132 R137-R139 R141-R144 R146-R151 R154-R161 R163-R178 R180 R182-R184 R186 R188 R189 R191 R193 R194 R196-R203 R206 R208-R210 R212-R216 R218 R221-R227 R231-R233 R235 R236 R238 R239 R241 R244 R245 R247-R250 R252 R254-R257 R259 R266-R282 R289 R290 R293 R294 R297 R299-R302 R304-R308 R310 R311 R317 R320-R322 R327-R329 R331-R333 R340-R344 R346 R349 R351 R352 R355-R363 R366-R369 R376 R378 R384 R386 R394 R396 R399-R401 R403 R407-R411 R415 R416 R418-R422 R427-R435 R439-R441 R451-R453 R457 R461 R463 R465 R468 R470 R479 R481 R489-R491 R493-R500 R502-R506 R512-R514 R517 R578 R581 R587 R588 R598 R780 R782 R816 R819 R821 R990 R991 R998-R1001 R1007-R1013 R1017 R1019 R1022-R1029 R1031 R1035 R1038-R1042 R1044-R1108 R1113-R1125 R1128 R1129 R1136-R1143 R1148 R1149 R1152 R1153 R1158 R1159 R1163-R1167 R1171-R1173 R1175 R1179-R1207 = R0402
D16 = DSMV
D17 = SOT323_213-2_1-1_3-2N7002W
HOLE1 = H-O158X118D158X118N
HOLE2 HOLE3 = H-C276D110P2
HOLE4 = H-C142X118D142X118N
HOLE5 = SPAD-ZXX-5
HOLE6 = H-ZXX-6
HOLE7 = H-TC276IC276BC315D110P2
HOLE8 = SPAD-S354NP
HOLE9 = H-C118D118N
HOLE10 = H-ZXX-2
HOLE11 = H-ZXX-1
HOLE12 = H-ZXX-13
HOLE13 = H-ZHX-1
HOLE14 = H-TC276IC197BC315D142X134P2
HOLE15 HOLE17 HOLE18 = SPAD-C315
HOLE16 = SPAD-ZHX-2
JP1-JP3 JP5 JP7 JP8 JP10-JP12 = SHORT3720
L4 PR137 PR139 PR162 PR183 PR194 R337 R450 R501 R507 R1005 R1037 R1144 R1150 = R0805
LED2 = LEDLTST-S326KGJRKT-3P-SMT
MR1 = SOT23_123-2_8-1_9
MR3 = SENSOR-1_3X0_9-5-4P
PC44 PC59 PC75 PC88 = CC7343
PD4 = D-DO-214AC
PD5 = D-TO277_213-6_1X4_3
PD6-PD8 PQ22 PQ24 PQ30 PQ35 Q24 Q39 Q43 = UMT_213-3-1_3
PJ1 = DCJK-2DC3079-007111F-2P
PJ2 = 50458-00801-V02-8P-L
PL1-PL3 PL6-PL8 = CHOKE-PCMC063T-3R3MN-SMT
PL4 PL5 = CHOKE-PCMC063T-R82MN-4P-SMT
PQ1 = IMD
PQ2 PQ3 PQ11 PQ12 PQ16 PQ18 PQ20 PQ21 PQ23 PQ27 PQ31-PQ34 PQ37 Q2 Q3 Q5 Q7 Q10-Q12 Q14-Q17 Q19 Q21-Q23 Q25 Q27 Q31-Q34 Q40-Q42 Q44 Q45 Q53 Q54 Q65 Q75-Q79 = SOT23_213-3_3-2
PQ4 PQ8 PQ9 PQ13 PQ14 PQ17 PQ29 = WDFN5-3_05X3_05-65
PQ6 PQ7 = POWER-5X6-1_27-7P
PQ10 = SO-8FL-5P-OA
PQ15 = POWER-5X5-1_27-5P
PQ36 PQ38 PQ39 Q1 Q6 Q13 Q35 Q36 Q38 U11 U16 = SC70-2_1-65-6P
PR10 PR19 PR22 PR23 PR38 PR60 PR61 PR110 PR114 PR117 PR118 PR121 PR135 PR140 PR148 PR150 PR200 PR210 PR213 R11-R16 R106 R109 R136 R181 R220 R295 R336 R339 R350 R382 R388-R390 R392 R671 R1018 R1145-R1147 R1209 = S0402
PR113 PR136 = RC3216
PR126 = R1206
PU1 = QFN28-4X4-4-29P-RT5041A
PU2 U38 = SOIC8-6-1_27
PU3 PU5 = QFN14-3X3-4-16P
PU4 PU6 = QFN32-4X4-4-33P-RT8171B
PU7 = TQFN20-3X3-4-21P
PU8 = PVQFN20-3_5X3_5-5-25P
R49 R312 R314-R316 R323-R326 R334 R338 R347 R353 R354 R364 R381 R414 R417 R423-R426 R436 R437 R444 R1014 R1043 = S0603
R313 R319 R365 R377 R385 R395 R405 R406 = S0805
RP1 = 10P8R
SW2 = SW-NTC031-AB1G-A160T-4P
SW3 = SW-DS-A40E-4P
T1 T4 T5 TP1 TP23-TP34 TP47-TP49 = TP2675
TP5 TP6 TP8 TP10 TP36-TP38 TP46 TP50-TP55 TP59-TP64 = TP2650
U1 U36 = SOT23-5-2_8-95-5P-1_3H
U4 = QFN48-6X6-4-49P-ALC280
U5 U14 = SOIC8-7_9-1_27
U7 = BGA1170-INTEL-BRASWELL
U8 = MSOP8-4_9-65
U9 = LQFP128-16X16-4-1_6H
U12 = SOT23-2_8-95-6P
U13 = TSSOP28-6_4-65-SLB9635TT
U15 U19 = VSSOP8-3_1-5-8P
U17 U18 = SC70-2_1-65-6P-0_95H
U20 = FBGA153-SAMSUNG-KLMBG4GEAC
U21 = LGA16-3X3-5
U23 = QFN24-4X4-5-25P-ALC5629
U24-U27 U31-U34 = BGA96-ELPIDA-EDJ4216EBBG-DJ-F
U35 = QFN28-5X5-5-29P-GL850G
U37 = SOT23-5
Y2 = XTL-3_2X2_5-2_2X1_7
Y3 = XTL-3_2X1_5-2_5-0_8H
Y4 = XTL-3_2X2_5-2_2X1_8-4P

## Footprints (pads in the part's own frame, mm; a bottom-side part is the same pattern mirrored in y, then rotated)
10P8R
  rect 0.305x1.092 smd: 1(-1.27,-0.85) 2(-0.635,-0.85) 3(0,-0.85) 4(0.635,-0.85) 5(1.27,-0.85) 6(1.27,0.85) 7(0.635,0.85) 8(0,0.85) 9(-0.635,0.85) 10(-1.27,0.85)
50281-0040N-001-4P-L
  rect 0.787x2.007 smd: 1(-1.875,4.05) 2(-0.625,4.05) 3(0.625,4.05) 4(1.875,4.05)
  rect 2.007x2.489 smd: 5(-4.075,0) 6(4.075,0)
50458-00801-V02-8P-L
  rect 0.559x1.295 smd: 1(-7,5.025) 2(-5,5.025) 3(-3,5.025) 4(-1,5.025) 5(1,5.025) 6(3,5.025) 7(5,5.025) 8(7,5.025)
  rect 1.295x2.057 smd: 9(-10.1,0) 10(10.1,0)
50584-0280N-V01-28P-L
  rect 0.61x1.092 smd: 1(-13.5,2.05) 2(-12.5,2.05) 3(-11.5,2.05) 4(-10.5,2.05) 5(-9.5,2.05) 6(-8.5,2.05) 7(-7.5,2.05) 8(-6.5,2.05) 9(-5.5,2.05) 10(-4.5,2.05) 11(-3.5,2.05) 12(-2.5,2.05) 13(-1.5,2.05) 14(-0.5,2.05) 15(0.5,2.05) 16(1.5,2.05) 17(2.5,2.05) 18(3.5,2.05) 19(4.5,2.05) 20(5.5,2.05) 21(6.5,2.05) 22(7.5,2.05) 23(8.5,2.05) 24(9.5,2.05) 25(10.5,2.05) 26(11.5,2.05) 27(12.5,2.05) 28(13.5,2.05)
  rect 2.159x2.997 smd: 29(-15.975,0) 30(15.975,0)
88513-0801-8P-L
  rect 0.508x1.295 smd: 1(-3.5,0) 2(-2.5,0) 3(-1.5,0) 4(-0.5,0) 5(0.5,0) 6(1.5,0) 7(2.5,0) 8(3.5,0)
  rect 1.803x1.397 smd: 9(-5.65,-2.8) 10(5.65,-2.8)
AF712L-A2G1T-12P-L-SMT
  rect 0.305x1.499 smd: 1(-2.75,2.75) 2(-2.25,2.75) 3(-1.75,2.75) 4(-1.25,2.75) 5(-0.75,2.75) 6(-0.25,2.75) 7(0.25,2.75) 8(0.75,2.75) 9(1.25,2.75) 10(1.75,2.75) 11(2.25,2.75) 12(2.75,2.75)
  rect 1.803x1.397 smd: 13(-4.4,0) 14(4.4,0)
BGA96-ELPIDA-EDJ4216EBBG-DJ-F
  round 0.356 smd: A1(-3.2,6) A2(-2.4,6) A3(-1.6,6) A7(1.6,6) A8(2.4,6) A9(3.2,6) B1(-3.2,5.2) B2(-2.4,5.2) B3(-1.6,5.2) B7(1.6,5.2) B8(2.4,5.2) B9(3.2,5.2) C1(-3.2,4.4) C2(-2.4,4.4) C3(-1.6,4.4) C7(1.6,4.4) C8(2.4,4.4) C9(3.2,4.4) D1(-3.2,3.6) D2(-2.4,3.6) D3(-1.6,3.6) D7(1.6,3.6) D8(2.4,3.6) D9(3.2,3.6) E1(-3.2,2.8) E2(-2.4,2.8) E3(-1.6,2.8) E7(1.6,2.8) E8(2.4,2.8) E9(3.2,2.8) F1(-3.2,2) F2(-2.4,2) F3(-1.6,2) F7(1.6,2) F8(2.4,2) F9(3.2,2) G1(-3.2,1.2) G2(-2.4,1.2) G3(-1.6,1.2) G7(1.6,1.2) G8(2.4,1.2) G9(3.2,1.2) H1(-3.2,0.4) H2(-2.4,0.4) H3(-1.6,0.4) H7(1.6,0.4) H8(2.4,0.4) H9(3.2,0.4) J1(-3.2,-0.4) J2(-2.4,-0.4) J3(-1.6,-0.4) J7(1.6,-0.4) J8(2.4,-0.4) J9(3.2,-0.4) K1(-3.2,-1.2) K2(-2.4,-1.2) K3(-1.6,-1.2) K7(1.6,-1.2) K8(2.4,-1.2) K9(3.2,-1.2) L1(-3.2,-2) L2(-2.4,-2) L3(-1.6,-2) L7(1.6,-2) L8(2.4,-2) L9(3.2,-2) M1(-3.2,-2.8) M2(-2.4,-2.8) M3(-1.6,-2.8) M7(1.6,-2.8) M8(2.4,-2.8) M9(3.2,-2.8) N1(-3.2,-3.6) N2(-2.4,-3.6) N3(-1.6,-3.6) N7(1.6,-3.6) N8(2.4,-3.6) N9(3.2,-3.6) P1(-3.2,-4.4) P2(-2.4,-4.4) P3(-1.6,-4.4) P7(1.6,-4.4) P8(2.4,-4.4) P9(3.2,-4.4) R1(-3.2,-5.2) R2(-2.4,-5.2) R3(-1.6,-5.2) R7(1.6,-5.2) R8(2.4,-5.2) R9(3.2,-5.2) T1(-3.2,-6) T2(-2.4,-6) T3(-1.6,-6) T7(1.6,-6) T8(2.4,-6) T9(3.2,-6)
